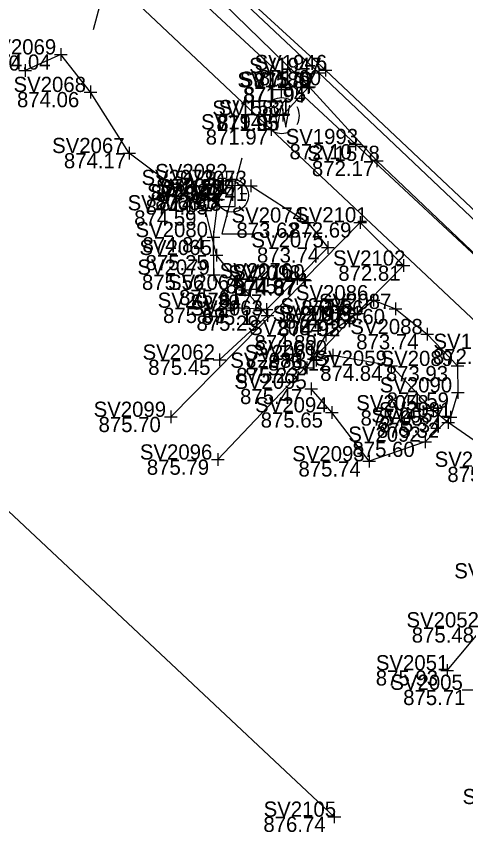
# Model space of a CAD drawing. Extents: x 1480001 to 1480402, y 379235 to 379603.
# Drawn here: x 1480045 to 1480080.5, y 379434.1 to 379498.7 of the extents above; entities that cross this region are included whole.
import ezdxf

# ---------------------------------------------------------------- set-up
doc = ezdxf.new("R2010")
doc.units = 0
for name, color, linetype in [('BD_X_Building', 7, 'Continuous'), ('LT_X_Poles', 7, 'Continuous'), ('PV_X_Curb', 7, 'Continuous'), ('PV_X_Steps', 7, 'Continuous'), ('PV_X_Walk', 7, 'Continuous'), ('RD_X_Cells', 7, 'Continuous'), ('SV_X_Break_Lines', 7, 'Continuous'), ('SV_X_Shot_Marker', 7, 'Continuous'), ('SV_X_Text_Elevation', 7, 'Continuous'), ('SV_X_Text_Name', 7, 'Continuous'), ('UT_X_Misc_Cells', 7, 'Continuous'), ('UT_X_Water', 7, 'Continuous'), ('UT_X_Water_Cells', 7, 'Continuous'), ('VG_X_Flower_Bed', 7, 'Continuous')]:
    doc.layers.add(name, color=color, linetype=linetype)

msp = doc.modelspace()

# ---------------------------------------------------------------- linework, layer by layer
at = {"layer": 'BD_X_Building'}
msp.add_line((1480070.116, 379435.596), (1480042.741, 379461.279), dxfattribs=at)
at = {"layer": 'LT_X_Poles'}
msp.add_lwpolyline([(1480062.831, 379487.558), (1480061.256, 379481.573), (1480063.619, 379481.573)], dxfattribs=at)
msp.add_circle((1480062.044, 379484.604), 1.3, dxfattribs=at)
at = {"layer": 'PV_X_Curb'}
for points in [[(1480135.19, 379432.332), (1480118.45, 379448.16), (1480110.152, 379455.954), (1480109.273, 379456.61), (1480100.92, 379464.722), (1480096.044, 379469.27), (1480093.779, 379471.437), (1480091.422, 379473.761), (1480089.145, 379475.876), (1480069.411, 379494.504), (1480056.455, 379506.379), (1480055.435, 379507.417), (1480042.302, 379520.019), (1480041.64, 379520.833), (1480030.984, 379530.729), (1480016.059, 379544.67)], [(1480135, 379431.897), (1480118.039, 379447.914), (1480109.91, 379455.647), (1480108.98, 379456.443), (1480100.472, 379464.439), (1480095.645, 379469.163), (1480093.387, 379471.311), (1480093.127, 379470.939), (1480088.623, 379475.041), (1480088.838, 379475.368), (1480068.906, 379494.276), (1480056.264, 379506.212), (1480055.202, 379507.245), (1480042.335, 379519.353), (1480041.39, 379520.138), (1480030.539, 379530.321), (1480016.21, 379543.914)]]:
    msp.add_lwpolyline(points, dxfattribs=at)
at = {"layer": 'PV_X_Steps'}
msp.add_lwpolyline([(1480067.746, 379477.99), (1480072.165, 379482.489), (1480075.578, 379479.079), (1480071.288, 379474.717)], dxfattribs=at)
at = {"layer": 'PV_X_Walk'}
for p, q in [((1480067.823, 379477.906), (1480057.214, 379467.144)), ((1480060.926, 379463.774), (1480071.315, 379474.711))]:
    msp.add_line(p, q, dxfattribs=at)
for points in [[(1480132.903, 379425.968), (1480114.834, 379442.96), (1480103.251, 379453.811), (1480091.01, 379465.628), (1480083.545, 379472.507), (1480065.123, 379489.824), (1480051.079, 379503.111), (1480050.67, 379503.609), (1480040.657, 379513.03), (1480041.273, 379513.837), (1480027.417, 379527.179), (1480013.329, 379540.204)], [(1480053.564, 379505.61), (1480071.797, 379488.664), (1480089.369, 379472.273), (1480095.978, 379465.936)]]:
    msp.add_lwpolyline(points, dxfattribs=at)
at = {"layer": 'RD_X_Cells'}
for p, q in [((1480060.679, 379485.698), (1480060.309, 379486.073)), ((1480061.644, 379486.009), (1480061.644, 379486.541)), ((1480062.977, 379486.073), (1480062.606, 379485.698)), ((1480060.601, 379484.736), (1480060.069, 379484.736)), ((1480061.644, 379484.729), (1480061.644, 379484.729)), ((1480063.219, 379484.736), (1480062.686, 379484.736)), ((1480060.679, 379483.761), (1480060.309, 379483.386)), ((1480061.644, 379483.449), (1480061.644, 379482.918)), ((1480062.977, 379483.386), (1480062.606, 379483.761))]:
    msp.add_line(p, q, dxfattribs=at)
msp.add_lwpolyline([(1480060.977, 379483.729), (1480062.309, 379483.729), (1480062.309, 379485.729), (1480060.977, 379485.729)], close=True, dxfattribs=at)
at = {"layer": 'SV_X_Break_Lines'}
for points in [[(1480061.053, 379471.656), (1480064.838, 379475.137), (1480063.063, 379477.168), (1480060.816, 379479.912), (1480059.959, 379483.437), (1480053.932, 379487.957), (1480050.898, 379492.776), (1480048.55, 379495.74), (1480045.746, 379494.465)], [(1480079.005, 379447.144), (1480081.842, 379450.534), (1480085.618, 379454.399), (1480087.323, 379457.733), (1480087.179, 379459.291), (1480084.148, 379463.202), (1480079.083, 379466.692), (1480077.899, 379467.657), (1480074.604, 379471.178), (1480070.008, 379471.999), (1480068.685, 379471.629)]]:
    msp.add_lwpolyline(points, dxfattribs=at)
at = {"layer": 'SV_X_Shot_Marker'}
for p, q in [((1480048.05, 379495.74), (1480049.05, 379495.74)), ((1480048.55, 379496.24), (1480048.55, 379495.24)), ((1480048.55, 379495.74), (1480048.55, 379495.74)), ((1480069.411, 379495.004), (1480069.411, 379494.004)), ((1480045.246, 379494.465), (1480046.246, 379494.465)), ((1480045.746, 379494.965), (1480045.746, 379493.965)), ((1480045.746, 379494.465), (1480045.746, 379494.465)), ((1480068.906, 379494.776), (1480068.906, 379493.776)), ((1480068.911, 379494.504), (1480069.911, 379494.504)), ((1480069.411, 379494.504), (1480069.411, 379494.504)), ((1480068.123, 379493.687), (1480068.123, 379492.687)), ((1480068.406, 379494.276), (1480069.406, 379494.276)), ((1480068.906, 379494.276), (1480068.906, 379494.276)), ((1480050.898, 379493.276), (1480050.898, 379492.276)), ((1480067.558, 379493.142), (1480068.558, 379493.142)), ((1480067.623, 379493.187), (1480068.623, 379493.187)), ((1480068.058, 379493.642), (1480068.058, 379492.642)), ((1480068.058, 379493.142), (1480068.058, 379493.142)), ((1480068.123, 379493.187), (1480068.123, 379493.187)), ((1480050.398, 379492.776), (1480051.398, 379492.776)), ((1480050.898, 379492.776), (1480050.898, 379492.776)), ((1480066.044, 379491.448), (1480066.044, 379490.448)), ((1480065.544, 379490.948), (1480066.544, 379490.948)), ((1480066.044, 379490.948), (1480066.044, 379490.948)), ((1480064.623, 379489.824), (1480065.623, 379489.824)), ((1480065.123, 379490.324), (1480065.123, 379489.324)), ((1480065.123, 379489.824), (1480065.123, 379489.824)), ((1480071.797, 379489.164), (1480071.797, 379488.164)), ((1480071.297, 379488.664), (1480072.297, 379488.664)), ((1480071.797, 379488.664), (1480071.797, 379488.664)), ((1480053.432, 379487.957), (1480054.432, 379487.957)), ((1480053.932, 379488.457), (1480053.932, 379487.457)), ((1480053.932, 379487.957), (1480053.932, 379487.957)), ((1480072.959, 379487.337), (1480073.959, 379487.337)), ((1480073.459, 379487.837), (1480073.459, 379486.837)), ((1480073.459, 379487.337), (1480073.459, 379487.337)), ((1480060.934, 379485.94), (1480060.934, 379484.94)), ((1480062.027, 379486.399), (1480062.027, 379485.399)), ((1480060.434, 379485.44), (1480061.434, 379485.44)), ((1480060.934, 379485.44), (1480060.934, 379485.44)), ((1480061.527, 379485.899), (1480062.527, 379485.899)), ((1480062.027, 379485.899), (1480062.027, 379485.899)), ((1480063.031, 379485.366), (1480064.031, 379485.366)), ((1480063.531, 379485.866), (1480063.531, 379484.866)), ((1480063.531, 379485.366), (1480063.531, 379485.366)), ((1480060.963, 379484.807), (1480060.963, 379483.807)), ((1480060.463, 379484.307), (1480061.463, 379484.307)), ((1480060.963, 379484.307), (1480060.963, 379484.307)), ((1480059.459, 379483.437), (1480060.459, 379483.437)), ((1480059.959, 379483.937), (1480059.959, 379482.937)), ((1480059.959, 379483.437), (1480059.959, 379483.437)), ((1480068.028, 379482.971), (1480068.028, 379481.971)), ((1480072.165, 379482.989), (1480072.165, 379481.989)), ((1480067.528, 379482.471), (1480068.528, 379482.471)), ((1480068.028, 379482.471), (1480068.028, 379482.471)), ((1480071.665, 379482.489), (1480072.665, 379482.489)), ((1480072.165, 379482.489), (1480072.165, 379482.489)), ((1480060.594, 379481.825), (1480060.594, 379480.825)), ((1480060.094, 379481.325), (1480061.094, 379481.325)), ((1480060.594, 379481.325), (1480060.594, 379481.325)), ((1480069.609, 379481.014), (1480069.609, 379480.014)), ((1480060.816, 379480.412), (1480060.816, 379479.412)), ((1480069.109, 379480.514), (1480070.109, 379480.514)), ((1480069.609, 379480.514), (1480069.609, 379480.514)), ((1480060.316, 379479.912), (1480061.316, 379479.912)), ((1480060.816, 379479.912), (1480060.816, 379479.912)), ((1480075.578, 379479.579), (1480075.578, 379478.579)), ((1480060.627, 379478.862), (1480060.627, 379477.862)), ((1480075.078, 379479.079), (1480076.078, 379479.079)), ((1480075.578, 379479.079), (1480075.578, 379479.079)), ((1480060.127, 379478.362), (1480061.127, 379478.362)), ((1480060.627, 379478.362), (1480060.627, 379478.362)), ((1480067.181, 379478.573), (1480067.181, 379477.573)), ((1480067.746, 379478.49), (1480067.746, 379477.49)), ((1480067.823, 379478.406), (1480067.823, 379477.406)), ((1480063.063, 379477.668), (1480063.063, 379476.668)), ((1480066.681, 379478.073), (1480067.681, 379478.073)), ((1480067.181, 379478.073), (1480067.181, 379478.073)), ((1480067.246, 379477.99), (1480068.246, 379477.99)), ((1480067.323, 379477.906), (1480068.323, 379477.906)), ((1480067.746, 379477.99), (1480067.746, 379477.99)), ((1480067.823, 379477.906), (1480067.823, 379477.906)), ((1480062.563, 379477.168), (1480063.563, 379477.168)), ((1480063.063, 379477.168), (1480063.063, 379477.168)), ((1480062.225, 379476.25), (1480062.225, 379475.25)), ((1480072.706, 379476.344), (1480073.706, 379476.344)), ((1480073.206, 379476.844), (1480073.206, 379475.844)), ((1480073.206, 379476.344), (1480073.206, 379476.344)), ((1480061.725, 379475.75), (1480062.725, 379475.75)), ((1480062.225, 379475.75), (1480062.225, 379475.75)), ((1480064.259, 379475.603), (1480065.259, 379475.603)), ((1480064.759, 379476.103), (1480064.759, 379475.103)), ((1480064.759, 379475.603), (1480064.759, 379475.603)), ((1480064.838, 379475.637), (1480064.838, 379474.637)), ((1480071.915, 379475.807), (1480071.915, 379474.807)), ((1480074.451, 379475.658), (1480075.451, 379475.658)), ((1480074.951, 379476.158), (1480074.951, 379475.158)), ((1480074.951, 379475.658), (1480074.951, 379475.658)), ((1480064.338, 379475.137), (1480065.338, 379475.137)), ((1480064.838, 379475.137), (1480064.838, 379475.137)), ((1480071.288, 379475.217), (1480071.288, 379474.217)), ((1480071.315, 379475.211), (1480071.315, 379474.211)), ((1480071.415, 379475.307), (1480072.415, 379475.307)), ((1480071.915, 379475.307), (1480071.915, 379475.307)), ((1480070.788, 379474.717), (1480071.788, 379474.717)), ((1480070.815, 379474.711), (1480071.815, 379474.711)), ((1480071.288, 379474.717), (1480071.288, 379474.717)), ((1480071.315, 379474.711), (1480071.315, 379474.711)), ((1480069.442, 379474.093), (1480069.442, 379473.093)), ((1480076.936, 379473.673), (1480077.936, 379473.673)), ((1480077.436, 379474.173), (1480077.436, 379473.173)), ((1480077.436, 379473.673), (1480077.436, 379473.673)), ((1480068.942, 379473.593), (1480069.942, 379473.593)), ((1480069.442, 379473.593), (1480069.442, 379473.593)), ((1480070.008, 379472.499), (1480070.008, 379471.499)), ((1480061.053, 379472.156), (1480061.053, 379471.156)), ((1480068.685, 379472.129), (1480068.685, 379471.129)), ((1480069.508, 379471.999), (1480070.508, 379471.999)), ((1480070.008, 379471.999), (1480070.008, 379471.999)), ((1480060.553, 379471.656), (1480061.553, 379471.656)), ((1480061.053, 379471.656), (1480061.053, 379471.656)), ((1480067.961, 379471.514), (1480067.961, 379470.514)), ((1480068.185, 379471.629), (1480069.185, 379471.629)), ((1480068.685, 379471.629), (1480068.685, 379471.629)), ((1480074.104, 379471.178), (1480075.104, 379471.178)), ((1480074.604, 379471.678), (1480074.604, 379470.678)), ((1480074.604, 379471.178), (1480074.604, 379471.178)), ((1480079.316, 379471.16), (1480080.316, 379471.16)), ((1480079.816, 379471.66), (1480079.816, 379470.66)), ((1480079.816, 379471.16), (1480079.816, 379471.16)), ((1480067.461, 379471.014), (1480068.461, 379471.014)), ((1480067.961, 379471.014), (1480067.961, 379471.014)), ((1480068.296, 379469.854), (1480068.296, 379468.854)), ((1480067.796, 379469.354), (1480068.796, 379469.354)), ((1480068.296, 379469.354), (1480068.296, 379469.354)), ((1480079.864, 379469.571), (1480079.864, 379468.571)), ((1480079.364, 379469.071), (1480080.364, 379469.071)), ((1480079.864, 379469.071), (1480079.864, 379469.071)), ((1480069.93, 379467.997), (1480069.93, 379466.997)), ((1480077.899, 379468.157), (1480077.899, 379467.157)), ((1480057.214, 379467.644), (1480057.214, 379466.644)), ((1480069.43, 379467.497), (1480070.43, 379467.497)), ((1480069.93, 379467.497), (1480069.93, 379467.497)), ((1480077.399, 379467.657), (1480078.399, 379467.657)), ((1480077.899, 379467.657), (1480077.899, 379467.657)), ((1480079.083, 379467.192), (1480079.083, 379466.192)), ((1480079.264, 379467.608), (1480079.264, 379466.608)), ((1480056.714, 379467.144), (1480057.714, 379467.144)), ((1480057.214, 379467.144), (1480057.214, 379467.144)), ((1480078.583, 379466.692), (1480079.583, 379466.692)), ((1480078.764, 379467.108), (1480079.764, 379467.108)), ((1480079.083, 379466.692), (1480079.083, 379466.692)), ((1480079.264, 379467.108), (1480079.264, 379467.108)), ((1480077.272, 379465.683), (1480077.272, 379464.683)), ((1480076.772, 379465.183), (1480077.772, 379465.183)), ((1480077.272, 379465.183), (1480077.272, 379465.183)), ((1480060.926, 379464.274), (1480060.926, 379463.274)), ((1480072.862, 379464.137), (1480072.862, 379463.137)), ((1480060.426, 379463.774), (1480061.426, 379463.774)), ((1480060.926, 379463.774), (1480060.926, 379463.774)), ((1480072.362, 379463.637), (1480073.362, 379463.637)), ((1480072.862, 379463.637), (1480072.862, 379463.637)), ((1480078.505, 379447.144), (1480079.505, 379447.144)), ((1480079.005, 379447.644), (1480079.005, 379446.644)), ((1480079.005, 379447.144), (1480079.005, 379447.144)), ((1480080.195, 379445.604), (1480081.195, 379445.604)), ((1480069.616, 379435.596), (1480070.616, 379435.596)), ((1480070.116, 379436.096), (1480070.116, 379435.096)), ((1480070.116, 379435.596), (1480070.116, 379435.596))]:
    msp.add_line(p, q, dxfattribs=at)
at = {"layer": 'UT_X_Misc_Cells'}
msp.add_line((1480052.702, 379503.686), (1480051.096, 379497.686), dxfattribs=at)
at = {"layer": 'UT_X_Water'}
msp.add_line((1480068.058, 379493.142), (1480066.044, 379490.948), dxfattribs=at)
msp.add_lwpolyline([(1480225.088, 379345.601), (1480208.322, 379361.342), (1480207.346, 379362.25), (1480199.528, 379369.768), (1480193.21, 379375.651), (1480182.823, 379385.139), (1480177.927, 379389.525), (1480169.423, 379398.321), (1480161.035, 379406.189), (1480144.924, 379421.019), (1480134.739, 379430.559), (1480121.485, 379441.998), (1480113.085, 379450.369), (1480106.418, 379456.915), (1480094.539, 379467.985), (1480089.15, 379472.551), (1480086.751, 379474.713), (1480073.459, 379487.337), (1480068.123, 379493.187), (1480050.678, 379510.207), (1480044.404, 379515.873)], dxfattribs=at)
at = {"layer": 'UT_X_Water_Cells'}
for p, q in [((1480065.963, 379492.31), (1480065.963, 379493.581)), ((1480066.598, 379492.946), (1480065.326, 379492.946)), ((1480065.963, 379490.91), (1480065.963, 379490.91))]:
    msp.add_line(p, q, dxfattribs=at)
msp.add_lwpolyline([(1480065.326, 379491.73), (1480065.645, 379490.006), (1480065.963, 379491.73), (1480066.283, 379490.006), (1480066.6, 379491.73)], dxfattribs=at)
for start, end in [(60.01836, 120.01574), (150.01836, 209.98164), (330.01836, 29.98164), (239.98426, 299.98164)]:
    msp.add_arc((1480065.963, 379490.911), 1.4, start, end, dxfattribs=at)
at = {"layer": 'VG_X_Flower_Bed'}
for points in [[(1480060.934, 379485.44), (1480063.531, 379485.366), (1480068.028, 379482.471), (1480069.609, 379480.514), (1480067.181, 379478.073), (1480064.759, 379475.603), (1480062.225, 379475.75), (1480060.627, 379478.362), (1480060.594, 379481.325), (1480060.963, 379484.307), (1480062.027, 379485.899)], [(1480067.961, 379471.014), (1480069.442, 379473.593), (1480071.915, 379475.307), (1480073.206, 379476.344), (1480074.951, 379475.658), (1480077.436, 379473.673), (1480079.816, 379471.16), (1480079.864, 379469.071), (1480079.264, 379467.108), (1480077.272, 379465.183), (1480072.862, 379463.637), (1480069.93, 379467.497), (1480068.296, 379469.354)]]:
    msp.add_lwpolyline(points, dxfattribs=at)

# ---------------------------------------------------------------- texts
at = {"layer": 'SV_X_Text_Elevation'}
for s, p in [('874.04', (1480042.834, 379494.54)), ('871.60', (1480064.158, 379493.304)), ('871.97', (1480063.757, 379493.076)), ('871.94', (1480062.919, 379491.942)), ('871.95', (1480062.974, 379491.987)), ('874.06', (1480045.097, 379491.576)), ('871.95', (1480060.814, 379489.71)), ('871.95', (1480060.895, 379489.748)), ('871.97', (1480059.974, 379488.624)), ('872.10', (1480066.582, 379487.464)), ('874.17', (1480048.793, 379486.757)), ('872.17', (1480068.348, 379486.137)), ('874.01', (1480055.642, 379484.24)), ('873.89', (1480056.396, 379484.699)), ('873.41', (1480058.334, 379484.166)), ('873.95', (1480056.003, 379483.529)), ('874.05', (1480055.238, 379483.107)), ('874.08', (1480056.309, 379483.405)), ('874.59', (1480054.337, 379482.237)), ('873.62', (1480062.397, 379481.271)), ('872.69', (1480066.553, 379481.289)), ('874.84', (1480054.991, 379480.125)), ('873.74', (1480064.016, 379479.314)), ('875.25', (1480055.232, 379478.712)), ('872.81', (1480070.428, 379477.879)), ('875.56', (1480054.949, 379477.162)), ('874.57', (1480061.569, 379476.873)), ('874.87', (1480062.134, 379476.79)), ('874.87', (1480062.211, 379476.706)), ('875.61', (1480057.875, 379475.968)), ('873.86', (1480067.509, 379475.144)), ('875.59', (1480056.613, 379474.55)), ('875.17', (1480059.629, 379474.403)), ('873.60', (1480069.206, 379474.458)), ('875.29', (1480059.245, 379473.937)), ('874.46', (1480066.218, 379474.107)), ('874.93', (1480065.657, 379473.517)), ('874.92', (1480065.693, 379473.511)), ('873.74', (1480071.843, 379472.473)), ('874.89', (1480063.82, 379472.393)), ('872.56', (1480077.886, 379471.307)), ('875.12', (1480064.888, 379470.799)), ('875.45', (1480055.441, 379470.456)), ('875.23', (1480063.101, 379470.429)), ('874.84', (1480069.001, 379469.978)), ('873.93', (1480074.175, 379469.96)), ('875.23', (1480062.377, 379469.814)), ('875.47', (1480062.684, 379468.154)), ('874.59', (1480074.242, 379467.871)), ('875.65', (1480064.308, 379466.297)), ('875.05', (1480072.183, 379466.457)), ('875.70', (1480051.526, 379465.944)), ('875.32', (1480073.471, 379465.492)), ('875.34', (1480073.652, 379465.908)), ('875.60', (1480071.546, 379463.983)), ('875.79', (1480055.333, 379462.574)), ('875.74', (1480067.288, 379462.437)), ('875.12', (1480079.028, 379462.002)), ('875.48', (1480076.22, 379449.334)), ('875.93', (1480073.383, 379445.944)), ('875.71', (1480075.545, 379444.404)), ('876.74', (1480064.523, 379434.396))]:
    msp.add_text(s, height=1.2, dxfattribs=at).set_placement(p)
at = {"layer": 'SV_X_Text_Name'}
for s, p in [('SV2069', (1480042.475, 379495.74)), ('SV2070', (1480039.614, 379494.465)), ('SV1946', (1480063.828, 379494.504)), ('SV1947', (1480063.398, 379494.276)), ('SV1580', (1480062.475, 379493.142)), ('SV1579', (1480062.653, 379493.187)), ('SV2068', (1480044.823, 379492.776)), ('SV1582', (1480060.493, 379490.91)), ('SV1581', (1480060.999, 379490.948)), ('SV1948', (1480059.606, 379489.824)), ('SV1993', (1480066.28, 379488.664)), ('SV2067', (1480047.866, 379487.957)), ('SV1578', (1480067.989, 379487.337)), ('SV2072', (1480054.916, 379485.44)), ('SV2082', (1480055.99, 379485.899)), ('SV2073', (1480057.503, 379485.366)), ('SV2071', (1480056.05, 379484.729)), ('SV2081', (1480055.35, 379484.307)), ('SV1588', (1480056.555, 379484.605)), ('SV2066', (1480053.818, 379483.437)), ('SV2074', (1480062.01, 379482.471)), ('SV2101', (1480067.025, 379482.489)), ('SV2080', (1480054.443, 379481.325)), ('SV2075', (1480063.581, 379480.514)), ('SV2065', (1480054.75, 379479.912)), ('SV2102', (1480070.014, 379479.079)), ('SV2079', (1480054.59, 379478.362)), ('SV2076', (1480061.078, 379478.073)), ('SV2098', (1480061.748, 379477.906)), ('SV2100', (1480062.068, 379477.99)), ('SV2064', (1480057.007, 379477.168)), ('SV2086', (1480067.084, 379476.344)), ('SV2078', (1480056.188, 379475.75)), ('SV2087', (1480068.904, 379475.658)), ('SV2077', (1480058.731, 379475.603)), ('SV2063', (1480058.772, 379475.137)), ('SV2085', (1480065.868, 379475.307)), ('SV2097', (1480065.249, 379474.711)), ('SV2103', (1480065.714, 379474.717)), ('SV2084', (1480063.405, 379473.593)), ('SV2088', (1480071.38, 379473.673)), ('SV1940', (1480077.933, 379472.507)), ('SV2060', (1480063.838, 379471.999)), ('SV2062', (1480054.997, 379471.656)), ('SV2061', (1480063.053, 379471.629)), ('SV2059', (1480068.548, 379471.178)), ('SV2089', (1480073.76, 379471.16)), ('SV2083', (1480061.914, 379471.014)), ('SV2095', (1480062.23, 379469.354)), ('SV2090', (1480073.694, 379469.071)), ('SV2094', (1480063.874, 379467.497)), ('SV2058', (1480071.843, 379467.657)), ('SV2099', (1480051.139, 379467.144)), ('SV2057', (1480073.036, 379466.692)), ('SV2091', (1480073.632, 379467.108)), ('SV2092', (1480071.216, 379465.183)), ('SV2096', (1480054.785, 379463.774)), ('SV2093', (1480066.796, 379463.637)), ('SV2056', (1480078.026, 379463.202)), ('SV2053', (1480079.571, 379454.399)), ('SV2052', (1480075.805, 379450.534)), ('SV2051', (1480073.392, 379447.144)), ('SV2005', (1480074.535, 379445.604)), ('SV2050', (1480080.226, 379436.591)), ('SV2105', (1480064.542, 379435.596))]:
    msp.add_text(s, height=1.2, dxfattribs=at).set_placement(p)

doc.saveas('drawing.dxf')
